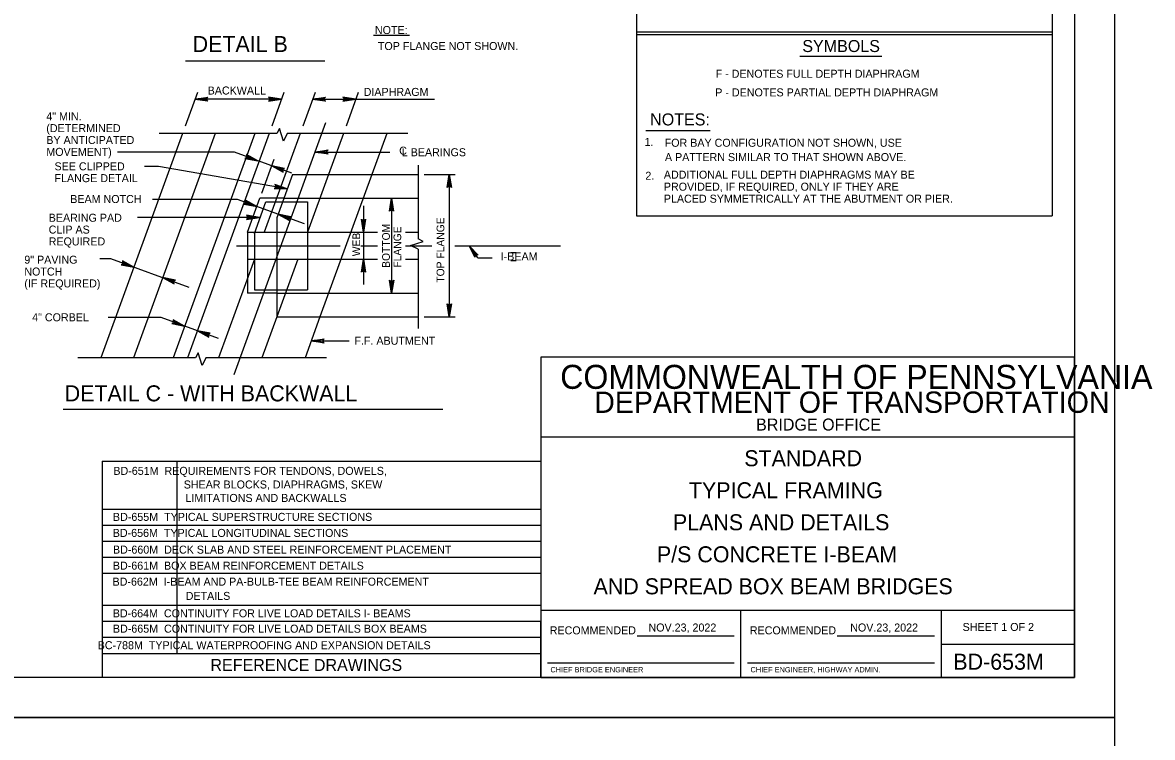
# Model space of a CAD drawing. Extents: x 639028 to 640031, y 298558 to 299746.
# Drawn here: x 639459.6 to 639883.1, y 299144.8 to 299412.7 of the extents above; entities that cross this region are included whole.
import ezdxf

# ---------------------------------------------------------------- set-up
doc = ezdxf.new("R2010")
doc.units = 0
for name, color, linetype in [('1', 7, 'Continuous'), ('DATES', 7, 'Continuous'), ('PLT-BNDY', 7, 'Continuous'), ('SIGNATORY TITLES', 7, 'Continuous')]:
    doc.layers.add(name, color=color, linetype=linetype)

msp = doc.modelspace()

# ---------------------------------------------------------------- linework, layer by layer
at = {"layer": '1'}
for p, q in [((639853.87, 299731.33), (639853.87, 299167.33)), ((639689.66, 299605.3), (639689.66, 299340.31)), ((639845.54, 299605.3), (639845.54, 299340.31)), ((639591.14, 299407.99), (639604.67, 299407.99)), ((639689.66, 299409.3), (639845.54, 299409.3)), ((639689.66, 299408.3), (639845.54, 299408.3)), ((639750.99, 299400.18), (639781.73, 299400.18)), ((639520.72, 299398.43), (639572.84, 299398.43)), ((639525.14, 299386.47), (639520.55, 299373.84)), ((639557.58, 299386.47), (639552.98, 299373.84)), ((639569.22, 299386.47), (639564.63, 299373.84)), ((639585.44, 299386.47), (639580.84, 299373.84)), ((639556.68, 299383.99), (639524.24, 299383.99)), ((639568.32, 299383.99), (639614.05, 299383.99)), ((639573.2, 299375.12), (639538.82, 299280.66)), ((639519.56, 299371.12), (639488.96, 299287.06)), ((639531.72, 299371.12), (639501.13, 299287.06)), ((639554.95, 299371.12), (639510.83, 299371.12)), ((639546.59, 299371.12), (639515.99, 299287.06)), ((639551.99, 299371.12), (639521.4, 299287.06)), ((639563.64, 299371.12), (639550.19, 299334.17)), ((639604.05, 299371.12), (639558.83, 299371.12)), ((639579.85, 299371.12), (639574.26, 299355.76)), ((639596.07, 299371.12), (639590.48, 299355.76)), ((639693.18, 299372.3), (639717.32, 299372.3)), ((639538.97, 299364.12), (639495.12, 299364.12)), ((639560.51, 299356.28), (639538.97, 299364.12)), ((639549.29, 299348.83), (639553.91, 299361.53)), ((639569.23, 299364.21), (639597.29, 299364.21)), ((639510.59, 299358.83), (639505.34, 299358.84)), ((639558.79, 299350.38), (639510.59, 299358.83)), ((639607.82, 299359.25), (639607.82, 299331.71)), ((639560.75, 299355.76), (639554.85, 299339.55)), ((639560.75, 299355.76), (639607.82, 299355.76)), ((639574.26, 299355.76), (639566.41, 299334.17)), ((639590.48, 299355.76), (639571.07, 299302.42)), ((639610.16, 299355.76), (639621.8, 299355.76)), ((639619.55, 299355.76), (639619.55, 299302.42)), ((639540.15, 299346.41), (639508.24, 299346.41)), ((639565.26, 299337.27), (639540.15, 299346.41)), ((639543.95, 299334.17), (639548.57, 299346.87)), ((639546.49, 299333.72), (639550.81, 299345.6)), ((639557.51, 299346.87), (639548.57, 299346.87)), ((639550.81, 299345.6), (639566.41, 299345.6)), ((639557.51, 299346.87), (639607.82, 299346.87)), ((639566.41, 299345.6), (639566.41, 299312.58)), ((639587.37, 299344.09), (639587.37, 299314.56)), ((639597.92, 299346.87), (639597.92, 299311.31)), ((639527.16, 299339.72), (639502.68, 299339.72)), ((639548.4, 299339.68), (639527.16, 299339.72)), ((639554.85, 299339.55), (639554.85, 299302.42)), ((639689.66, 299340.31), (639845.54, 299340.31)), ((639543.95, 299334.17), (639543.95, 299311.31)), ((639543.95, 299334.17), (639554.85, 299334.17)), ((639546.49, 299333.72), (639546.49, 299312.58)), ((639554.85, 299334.17), (639592.59, 299334.17)), ((639603.08, 299334.17), (639607.82, 299334.17)), ((639853.87, 299333.16), (639853.87, 299280.31)), ((639539.83, 299329.09), (639578.67, 299329.09)), ((639586.36, 299329.09), (639592.59, 299329.09)), ((639603.08, 299329.09), (639613.01, 299329.09)), ((639607.82, 299327.84), (639607.82, 299298.06)), ((639621.68, 299329.09), (639661.17, 299329.09)), ((639630.21, 299324.59), (639627.08, 299328.96)), ((639642.58, 299326.59), (639644.58, 299326.59)), ((639492.68, 299324.19), (639488.57, 299324.19)), ((639522.08, 299313.48), (639492.68, 299324.19)), ((639546.49, 299324.01), (639533.04, 299287.06)), ((639543.95, 299324.01), (639554.85, 299324.01)), ((639554.85, 299324.01), (639592.59, 299324.01)), ((639562.71, 299324.01), (639554.85, 299302.42)), ((639603.08, 299324.01), (639607.82, 299324.01)), ((639630.21, 299324.59), (639635.58, 299324.59)), ((639642.58, 299323.59), (639644.58, 299323.59)), ((639554.85, 299311.31), (639543.95, 299311.31)), ((639546.49, 299312.58), (639566.41, 299312.58)), ((639554.85, 299311.31), (639607.82, 299311.31)), ((639511.51, 299302.17), (639491.69, 299302.17)), ((639533.06, 299294.33), (639511.51, 299302.17)), ((639554.85, 299302.42), (639549.26, 299287.06)), ((639554.85, 299302.42), (639607.82, 299302.42)), ((639571.07, 299302.42), (639565.48, 299287.06)), ((639610.16, 299302.42), (639621.8, 299302.42)), ((639567.78, 299293.39), (639582.07, 299293.39)), ((639524.36, 299287.06), (639480.24, 299287.06)), ((639573.46, 299287.06), (639528.23, 299287.06)), ((639653.87, 299287.33), (639653.87, 299167.33)), ((639853.87, 299287.33), (639653.87, 299287.33)), ((639853.87, 299167.33), (639853.87, 299287.33)), ((639853.87, 299280.31), (639853.87, 299287.33)), ((639474.83, 299267.89), (639617.12, 299267.89)), ((639853.87, 299257.33), (639653.87, 299257.33)), ((639489.47, 299248.33), (639489.47, 299167.33)), ((639489.47, 299248.33), (639653.87, 299248.33)), ((639517.47, 299248.33), (639517.47, 299176.33)), ((639489.47, 299230.33), (639653.87, 299230.33)), ((639489.47, 299224.33), (639653.87, 299224.33)), ((639489.47, 299218.33), (639653.87, 299218.33)), ((639489.47, 299212.33), (639653.87, 299212.33)), ((639489.47, 299206.33), (639653.87, 299206.33)), ((639489.47, 299194.33), (639653.87, 299194.33)), ((639853.87, 299192.33), (639653.87, 299192.33)), ((639728.87, 299167.33), (639728.87, 299192.33)), ((639803.87, 299192.33), (639803.87, 299167.33)), ((639489.47, 299188.33), (639653.87, 299188.33)), ((639653.87, 299167.33), (639653.87, 299188.33)), ((639689.96, 299182.83), (639726.37, 299182.83)), ((639764.96, 299182.83), (639801.37, 299182.83)), ((639489.47, 299182.33), (639653.87, 299182.33)), ((639803.87, 299179.83), (639853.87, 299179.83)), ((639489.47, 299176.33), (639653.87, 299176.33)), ((639656.37, 299172.83), (639726.37, 299172.83)), ((639731.37, 299172.83), (639801.37, 299172.83)), ((639853.87, 299167.33), (639067.87, 299167.33)), ((639653.87, 299167.33), (639853.87, 299167.33))]:
    msp.add_line(p, q, dxfattribs=at)
for points in [[(639528.86, 299383.42), (639528.68, 299383.75), (639524.24, 299383.99), (639528.86, 299383.42), (639529.09, 299383.21), (639524.24, 299383.99), (639528.68, 299384.21), (639528.84, 299384.54), (639524.24, 299383.99), (639529.09, 299384.76), (639528.84, 299384.54)], [(639552.06, 299383.42), (639552.24, 299383.75), (639556.68, 299383.99), (639552.06, 299383.42), (639551.83, 299383.21), (639556.68, 299383.99), (639552.24, 299384.21), (639552.08, 299384.54), (639556.68, 299383.99), (639551.83, 299384.76), (639552.08, 299384.54)], [(639572.94, 299383.42), (639572.76, 299383.75), (639568.32, 299383.99), (639572.94, 299383.42), (639573.17, 299383.21), (639568.32, 299383.99), (639572.76, 299384.21), (639572.92, 299384.54), (639568.32, 299383.99), (639573.17, 299384.76), (639572.92, 299384.54)], [(639579.93, 299383.42), (639580.1, 299383.75), (639584.54, 299383.99), (639579.93, 299383.42), (639579.69, 299383.21), (639584.54, 299383.99), (639580.1, 299384.21), (639579.94, 299384.54), (639584.54, 299383.99), (639579.69, 299384.76), (639579.94, 299384.54)], [(639558.83, 299371.12), (639557.45, 299368.24), (639555.95, 299372.99), (639554.95, 299371.12)], [(639573.84, 299363.63), (639573.67, 299363.96), (639569.23, 299364.21), (639573.84, 299363.63), (639574.08, 299363.43), (639569.23, 299364.21), (639573.67, 299364.43), (639573.83, 299364.76), (639569.23, 299364.21), (639574.08, 299364.98), (639573.83, 299364.76)], [(639543.24, 299361.95), (639543.52, 299362.21), (639547.77, 299360.92), (639543.24, 299361.95), (639542.95, 299361.84), (639547.77, 299360.92), (639543.68, 299362.64), (639543.64, 299363.01), (639547.77, 299360.92), (639543.48, 299363.3), (639543.64, 299363.01)], [(639557.53, 299357.98), (639557.25, 299357.73), (639552.99, 299359.02), (639557.53, 299357.98), (639557.82, 299358.09), (639552.99, 299359.02), (639557.09, 299357.29), (639557.13, 299356.93), (639552.99, 299359.02), (639557.29, 299356.63), (639557.13, 299356.93)], [(639554.15, 299350.63), (639554.38, 299350.93), (639558.79, 299350.38), (639554.15, 299350.63), (639553.88, 299350.48), (639558.79, 299350.38), (639554.46, 299351.39), (639554.36, 299351.74), (639558.79, 299350.38), (639554.16, 299352), (639554.36, 299351.74)], [(639618.97, 299351.15), (639619.31, 299351.32), (639619.55, 299355.76), (639618.97, 299351.15), (639618.77, 299350.91), (639619.55, 299355.76), (639619.77, 299351.32), (639620.1, 299351.16), (639619.55, 299355.76), (639620.32, 299350.91), (639620.1, 299351.16)], [(639542.91, 299344.79), (639543.18, 299345.05), (639547.44, 299343.76), (639542.91, 299344.79), (639542.61, 299344.68), (639547.44, 299343.76), (639543.34, 299345.48), (639543.3, 299345.85), (639547.44, 299343.76), (639543.15, 299346.14), (639543.3, 299345.85)], [(639597.34, 299342.26), (639597.67, 299342.43), (639597.92, 299346.87), (639597.34, 299342.26), (639597.13, 299342.02), (639597.92, 299346.87), (639598.14, 299342.43), (639598.47, 299342.27), (639597.92, 299346.87), (639598.69, 299342.02), (639598.47, 299342.27)], [(639543.78, 299339.18), (639543.96, 299339.51), (639548.4, 299339.68), (639543.78, 299339.18), (639543.54, 299338.98), (639548.4, 299339.68), (639543.97, 299339.97), (639543.81, 299340.31), (639548.4, 299339.68), (639543.56, 299340.53), (639543.81, 299340.31)], [(639559.87, 299339.85), (639559.59, 299339.6), (639555.33, 299340.88), (639559.87, 299339.85), (639560.16, 299339.96), (639555.33, 299340.88), (639559.43, 299339.16), (639559.47, 299338.79), (639555.33, 299340.88), (639559.63, 299338.5), (639559.47, 299338.79)], [(639587.95, 299338.78), (639587.62, 299338.61), (639587.37, 299334.17), (639587.95, 299338.78), (639588.15, 299339.02), (639587.37, 299334.17), (639587.15, 299338.61), (639586.82, 299338.77), (639587.37, 299334.17), (639586.6, 299339.02), (639586.82, 299338.77)], [(639607.82, 299327.84), (639604.94, 299329.21), (639609.69, 299330.71), (639607.82, 299331.71)], [(639629.08, 299325.09), (639629.33, 299325.34), (639627.08, 299328.96), (639629.08, 299325.09), (639629.08, 299324.84), (639627.08, 299328.96), (639629.71, 299325.59), (639629.96, 299325.71), (639627.08, 299328.96), (639630.33, 299325.59), (639629.96, 299325.71)], [(639496.79, 299322.07), (639497.07, 299322.33), (639501.33, 299321.04), (639496.79, 299322.07), (639496.5, 299321.96), (639501.33, 299321.04), (639497.23, 299322.76), (639497.19, 299323.13), (639501.33, 299321.04), (639497.03, 299323.42), (639497.19, 299323.13)], [(639586.79, 299319.4), (639587.13, 299319.57), (639587.37, 299324.01), (639586.79, 299319.4), (639586.59, 299319.16), (639587.37, 299324.01), (639587.59, 299319.57), (639587.92, 299319.41), (639587.37, 299324.01), (639588.14, 299319.16), (639587.92, 299319.41)], [(639516.6, 299316.09), (639516.33, 299315.84), (639512.07, 299317.13), (639516.6, 299316.09), (639516.89, 299316.2), (639512.07, 299317.13), (639516.16, 299315.4), (639516.2, 299315.04), (639512.07, 299317.13), (639516.36, 299314.75), (639516.2, 299315.04)], [(639598.5, 299315.92), (639598.16, 299315.75), (639597.92, 299311.31), (639598.5, 299315.92), (639598.7, 299316.16), (639597.92, 299311.31), (639597.7, 299315.75), (639597.37, 299315.91), (639597.92, 299311.31), (639597.15, 299316.16), (639597.37, 299315.91)], [(639620.13, 299307.03), (639619.8, 299306.86), (639619.55, 299302.42), (639620.13, 299307.03), (639620.33, 299307.27), (639619.55, 299302.42), (639619.33, 299306.86), (639619, 299307.02), (639619.55, 299302.42), (639618.78, 299307.27), (639619, 299307.02)], [(639515.79, 299300), (639516.07, 299300.25), (639520.32, 299298.96), (639515.79, 299300), (639515.5, 299299.89), (639520.32, 299298.96), (639516.23, 299300.69), (639516.19, 299301.05), (639520.32, 299298.96), (639516.03, 299301.35), (639516.19, 299301.05)], [(639529.63, 299296.19), (639529.35, 299295.94), (639525.1, 299297.23), (639529.63, 299296.19), (639529.92, 299296.3), (639525.1, 299297.23), (639529.19, 299295.5), (639529.23, 299295.14), (639525.1, 299297.23), (639529.39, 299294.84), (639529.23, 299295.14)], [(639572.39, 299292.81), (639572.22, 299293.15), (639567.78, 299293.39), (639572.39, 299292.81), (639572.63, 299292.61), (639567.78, 299293.39), (639572.22, 299293.61), (639572.38, 299293.94), (639567.78, 299293.39), (639572.63, 299294.16), (639572.38, 299293.94)], [(639528.23, 299287.06), (639526.86, 299284.19), (639525.36, 299288.94), (639524.36, 299287.06)]]:
    msp.add_lwpolyline(points, dxfattribs=at)
at = {"layer": 'PLT-BNDY'}
for points in [[(639027.87, 299746.33), (639868.87, 299746.33), (639868.87, 299152.33), (639027.87, 299152.33)], [(639027.87, 299152.33), (639868.87, 299152.33), (639868.87, 298558.33), (639027.87, 298558.33)]]:
    msp.add_lwpolyline(points, close=True, dxfattribs=at)

# ---------------------------------------------------------------- texts
at = {"layer": '1'}
for s, height, p in [('NOTE:', 3, (639591.66, 299408.43)), ('DETAIL B', 6, (639523.34, 299401.68)), (' TOP FLANGE NOT SHOWN.', 3, (639591.66, 299402.43)), ('SYMBOLS', 4.5, (639751.88, 299401.68)), ('F - DENOTES FULL DEPTH DIAPHRAGM', 3, (639719.38, 299392.05)), ('BACKWALL', 3, (639528.96, 299385.76)), ('DIAPHRAGM', 3, (639587.45, 299385.23)), ('P - DENOTES PARTIAL DEPTH DIAPHRAGM', 3, (639719.25, 299385.05)), ('4" MIN.', 3, (639468.49, 299376.09)), ('NOTES:', 4.5, (639694.83, 299374.17)), ('(DETERMINED', 3, (639468.49, 299371.65)), ('BY ANTICIPATED', 3, (639468.49, 299367.21)), ('1.', 3, (639692.73, 299366.48)), ('FOR BAY CONFIGURATION NOT SHOWN, USE', 3, (639700.28, 299366.18)), ('MOVEMENT)', 3, (639468.49, 299362.76)), ('C', 3, (639600.76, 299363.22)), ('L BEARINGS', 3, (639601.73, 299362.62)), ('A PATTERN SIMILAR TO THAT SHOWN ABOVE.', 3, (639700.38, 299360.81)), ('SEE CLIPPED', 3, (639471.56, 299357.35)), ('2.', 3, (639693.04, 299353.82)), ('ADDITIONAL FULL DEPTH DIAPHRAGMS MAY BE', 3, (639699.97, 299354.22)), ('FLANGE DETAIL', 3, (639471.56, 299352.91)), ('PROVIDED, IF REQUIRED, ONLY IF THEY ARE', 3, (639699.97, 299349.72)), ('BEAM NOTCH', 3, (639477.45, 299345.09)), ('PLACED SYMMETRICALLY AT THE ABUTMENT OR PIER.', 3, (639699.97, 299345.22)), ('BEARING PAD', 3, (639469.38, 299338.08)), ('CLIP AS', 3, (639469.38, 299333.64)), ('REQUIRED', 3, (639469.38, 299329.2)), ('  I-BEAM', 3, (639636.58, 299323.59)), ('9" PAVING', 3, (639460.24, 299322.35)), ('NOTCH', 3, (639460.24, 299317.91)), ('(IF REQUIRED)', 3, (639460.24, 299313.47)), ('4" CORBEL', 3, (639463.18, 299300.77)), ('F.F. ABUTMENT', 3, (639583.97, 299291.99)), ('COMMONWEALTH OF PENNSYLVANIA', 9, (639661.12, 299275.45)), ('DETAIL C - WITH BACKWALL', 6, (639475.39, 299270.77)), ('DEPARTMENT OF TRANSPORTATION', 8.0002, (639673.87, 299266.45)), ('BRIDGE OFFICE', 4.5, (639734.55, 299259.83)), ('STANDARD', 6, (639730.12, 299246.45)), ('BD-651M  REQUIREMENTS FOR TENDONS, DOWELS,', 3, (639493.62, 299243.22)), ('SHEAR BLOCKS, DIAPHRAGMS, SKEW', 3, (639519.99, 299238.11)), ('TYPICAL FRAMING', 6, (639709.37, 299234.45)), ('LIMITATIONS AND BACKWALLS', 3, (639520.63, 299233.07)), ('BD-655M  TYPICAL SUPERSTRUCTURE SECTIONS', 3, (639493.46, 299225.97)), ('PLANS AND DETAILS', 6, (639703.37, 299222.45)), ('BD-656M  TYPICAL LONGITUDINAL SECTIONS', 3, (639493.39, 299219.96)), ('BD-660M  DECK SLAB AND STEEL REINFORCEMENT PLACEMENT', 3, (639493.47, 299213.7)), ('P/S CONCRETE I-BEAM', 6, (639697.37, 299210.45)), ('BD-661M  BOX BEAM REINFORCEMENT DETAILS', 3, (639493.43, 299207.7)), ('BD-662M  I-BEAM AND PA-BULB-TEE BEAM REINFORCEMENT', 3, (639493.31, 299201.7)), ('AND SPREAD BOX BEAM BRIDGES', 6, (639673.62, 299198.45)), ('DETAILS', 3, (639520.73, 299196.36)), ('BD-664M  CONTINUITY FOR LIVE LOAD DETAILS I- BEAMS', 3, (639493.4, 299189.83)), ('BD-665M  CONTINUITY FOR LIVE LOAD DETAILS BOX BEAMS', 3, (639493.44, 299184.08)), ('SHEET 1 OF 2', 3, (639811.97, 299184.72)), ('RECOMMENDED', 3, (639657.2, 299183.45)), ('RECOMMENDED', 3, (639732.2, 299183.45)), ('   BC-788M  TYPICAL WATERPROOFING AND EXPANSION DETAILS', 3, (639484.4, 299177.88)), ('REFERENCE DRAWINGS', 4.5, (639530, 299169.71)), ('BD-653M', 6, (639808.5, 299170.2))]:
    msp.add_text(s, height=height, dxfattribs=at).set_placement(p)
for s, p in [('TOP FLANGE', (639617.67, 299315.25)), ('BOTTOM', (639597.26, 299320.8)), ('FLANGE', (639601.53, 299320.88)), ('WEB', (639586.13, 299325.16))]:
    msp.add_text(s, height=2.886, rotation=90, dxfattribs=at).set_placement(p)
at = {"layer": 'DATES'}
for p in [(639694.21, 299184.51), (639769.83, 299184.51)]:
    msp.add_text('NOV.23, 2022', height=3, dxfattribs=at).set_placement(p)
at = {"layer": 'SIGNATORY TITLES'}
for s, p in [('CHIEF BRIDGE ENGINEER', (639657.46, 299169.2)), ('CHIEF ENGINEER, HIGHWAY ADMIN.', (639732.46, 299169.2))]:
    msp.add_text(s, height=2, dxfattribs=at).set_placement(p)

doc.saveas('drawing.dxf')
